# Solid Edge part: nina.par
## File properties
Author: Georg
Template: Iso Part.par
Last saved by: Kalle
Revision: 6
Application: Solid Edge
Accuracy: 0,990
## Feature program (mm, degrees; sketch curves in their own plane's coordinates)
sketch for "unnamed Protrusion 1" plane through (0, 0, 0) normal (0, 0, 1) x-axis (1, 0, 0)
  line (-0.0242, -13.5) -> (19.9758, -13.5)
  line (19.9758, -13.5) -> (19.9758, 13.5)
  line (19.9758, 13.5) -> (-0.0242, 13.5)
  line (-0.0242, 13.5) -> (-0.0242, -13.5)
  dimension (linear) = 0.0242
  dimension (linear) = 0.0242
extrude "unnamed Protrusion 1" add finite 13 along +normal
sketch for "ExtrudedCutout_2" plane through (0, -13.5, 6.5) normal (0, -1, 0) x-axis (1, 0, 0)
  line (-0.0242, 6.5) -> (19.9758, -5.5)
extrude "ExtrudedCutout_2" cut finite 42.5757 along -normal
sketch for "ExtrudedCutout_4" plane through (0, 0, 0) normal (0, 0, 1) x-axis (1, 0, 0)
extrude "ExtrudedCutout_4" cut finite 116.0317 symmetric
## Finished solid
Body 1: solid body, 6 faces, 12 edges, 8 vertices.
  Faces by surface: plane 6
  Edges by curve: line 12
Bounding box of the edges (mm): 20.000 x 27.000 x 13.000, from (-0.0242, -13.5, 0) to (19.9758, 13.5, 13).
Planar faces by outward normal: +x 1, -x 1, -z 1, oblique 3
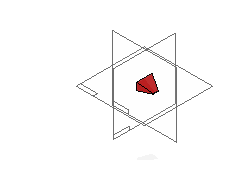
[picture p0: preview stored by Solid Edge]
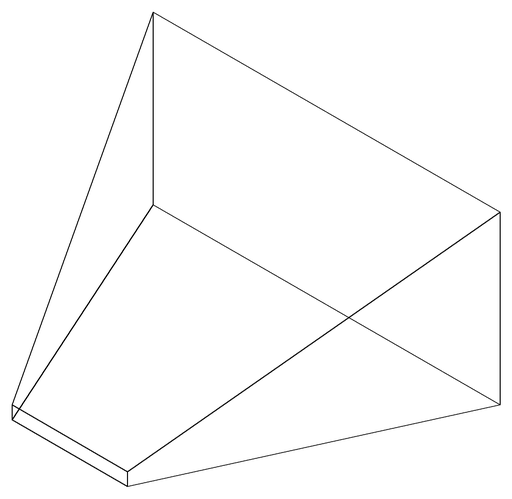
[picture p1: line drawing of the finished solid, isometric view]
